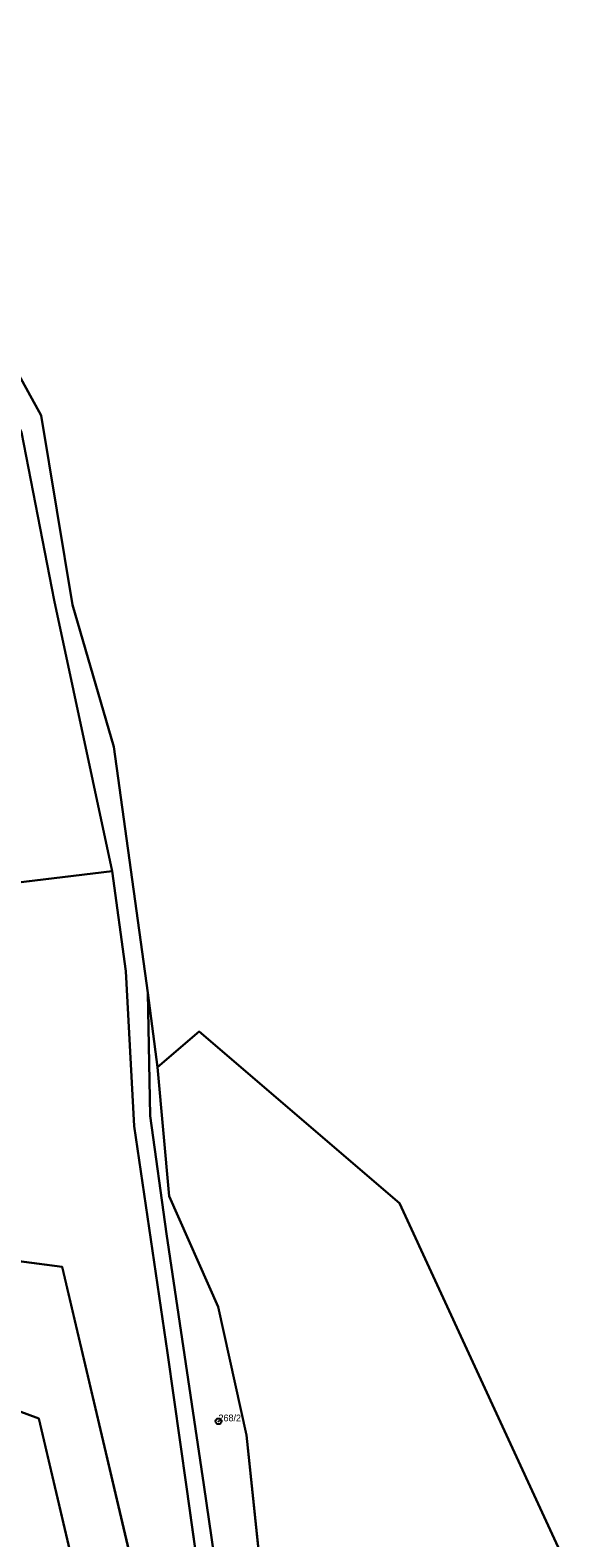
# Model space of a CAD drawing. Extents: x -652854 to -650068, y -1097661 to -1095417.
# Drawn here: x -651693.7 to -651554.5, y -1096486.9 to -1096107.3 of the extents above; entities that cross this region are included whole.
import ezdxf

# ---------------------------------------------------------------- set-up
doc = ezdxf.new("R2010")
doc.units = 0
for name, color, linetype in [('Definiční body parcel', 7, 'Continuous'), ('Hranice parcel', 7, 'Continuous'), ('Obvody jako plochy', 7, 'Continuous'), ('Parcelní čísla', 7, 'Continuous')]:
    doc.layers.add(name, color=color, linetype=linetype)

msp = doc.modelspace()

# ---------------------------------------------------------------- linework, layer by layer
at = {"layer": 'Definiční body parcel'}
for radius in [0.75, 0.0327]:
    msp.add_circle((-651646.29, -1096457.52), radius, dxfattribs=at)
at = {"layer": 'Hranice parcel'}
for p, q in [((-651690.95, -1096204.28), (-651728.47, -1096136.15)), ((-651683.01, -1096251.95), (-651690.95, -1096204.28)), ((-651695.89, -1096208.49), (-651687.67, -1096250.83)), ((-651687.67, -1096250.83), (-651673.04, -1096319.05)), ((-651672.67, -1096287.69), (-651683.01, -1096251.95)), ((-651664.09, -1096349.66), (-651672.67, -1096287.69)), ((-651673.04, -1096319.05), (-651710.67, -1096323.58)), ((-651673.04, -1096319.05), (-651669.61, -1096344.23)), ((-651669.61, -1096344.23), (-651667.53, -1096383.22)), ((-651664.09, -1096349.66), (-651663.46, -1096380.62)), ((-651661.63, -1096368.34), (-651664.09, -1096349.66)), ((-651651.15, -1096359.41), (-651661.63, -1096368.34)), ((-651600.66, -1096402.57), (-651651.15, -1096359.41)), ((-651658.71, -1096400.88), (-651661.63, -1096368.34)), ((-651663.46, -1096380.62), (-651659.4, -1096410.34)), ((-651667.53, -1096383.22), (-651659.12, -1096440.24)), ((-651646.4, -1096428.72), (-651658.71, -1096400.88)), ((-651555.25, -1096501.03), (-651600.66, -1096402.57)), ((-651685.67, -1096418.62), (-651785.42, -1096405.64)), ((-651659.4, -1096410.34), (-651650.01, -1096473.52)), ((-651663.59, -1096512.32), (-651685.67, -1096418.62)), ((-651639.25, -1096460.97), (-651646.4, -1096428.72)), ((-651691.55, -1096456.85), (-651747.93, -1096435.93)), ((-651654.35, -1096474.04), (-651659.12, -1096440.24)), ((-651666.79, -1096561.93), (-651691.55, -1096456.85)), ((-651634.91, -1096501.67), (-651639.25, -1096460.97)), ((-651650.01, -1096473.52), (-651636.3, -1096567.46)), ((-651654.35, -1096474.04), (-651642.8, -1096556.06))]:
    msp.add_line(p, q, dxfattribs=at)
at = {"layer": 'Obvody jako plochy'}
for points in [[(-651553.76, -1096093.05), (-651577.07, -1096086.78), (-651601.75, -1096075.97), (-651649.43, -1096071.53), (-651700.81, -1096041.54), (-651701.19, -1096046.05), (-651707.42, -1096048.55), (-651714.68, -1096051.04), (-651726.63, -1096058.67), (-651740.88, -1096077.97), (-651742.82, -1096091.89), (-651739.5, -1096109.16), (-651728.47, -1096136.15), (-651690.95, -1096204.28), (-651683.01, -1096251.95), (-651672.67, -1096287.69), (-651664.09, -1096349.66), (-651661.63, -1096368.34), (-651651.15, -1096359.41), (-651600.66, -1096402.57), (-651555.25, -1096501.03)], [(-651636.3, -1096567.46), (-651650.01, -1096473.52), (-651659.4, -1096410.34), (-651663.46, -1096380.62), (-651664.09, -1096349.66), (-651672.67, -1096287.69), (-651683.01, -1096251.95), (-651690.95, -1096204.28), (-651728.47, -1096136.15), (-651739.5, -1096109.16), (-651749.8, -1096112.77), (-651748.58, -1096115.33), (-651744.91, -1096121.76), (-651735.18, -1096138.78), (-651695.89, -1096208.49), (-651687.67, -1096250.83), (-651673.04, -1096319.05), (-651669.61, -1096344.23), (-651667.53, -1096383.22), (-651659.12, -1096440.24), (-651654.35, -1096474.04), (-651642.8, -1096556.06)], [(-651555.25, -1096501.03), (-651600.66, -1096402.57), (-651651.15, -1096359.41), (-651661.63, -1096368.34), (-651658.71, -1096400.88), (-651646.4, -1096428.72), (-651639.25, -1096460.97), (-651634.91, -1096501.67)]]:
    msp.add_lwpolyline(points, dxfattribs=at)
for points in [[(-651673.04, -1096319.05), (-651687.67, -1096250.83), (-651695.89, -1096208.49), (-651739.47, -1096210.32), (-651726.66, -1096252.14), (-651714.88, -1096279.19), (-651710.67, -1096323.58)], [(-651659.51, -1096555.13), (-651646.41, -1096555.8), (-651642.8, -1096556.06), (-651654.35, -1096474.04), (-651659.12, -1096440.24), (-651667.53, -1096383.22), (-651669.61, -1096344.23), (-651673.04, -1096319.05), (-651710.67, -1096323.58), (-651775.7, -1096331.44), (-651785.42, -1096405.64), (-651685.67, -1096418.62), (-651663.59, -1096512.32)], [(-651663.46, -1096380.62), (-651659.4, -1096410.34), (-651650.01, -1096473.52), (-651636.3, -1096567.46), (-651634.35, -1096543.17), (-651634.91, -1096501.67), (-651639.25, -1096460.97), (-651646.4, -1096428.72), (-651658.71, -1096400.88), (-651661.63, -1096368.34), (-651664.09, -1096349.66)], [(-651659.51, -1096555.13), (-651663.59, -1096512.32), (-651685.67, -1096418.62), (-651785.42, -1096405.64), (-651788.76, -1096431.88), (-651795.6, -1096461.91), (-651799.02, -1096481.47), (-651796.23, -1096492.24), (-651783.44, -1096503.05), (-651773.01, -1096517.88), (-651753.12, -1096532.75), (-651747.93, -1096435.93), (-651691.55, -1096456.85), (-651666.79, -1096561.93)], [(-651753.12, -1096532.75), (-651718.02, -1096559.55), (-651698.58, -1096568.61), (-651684.26, -1096565.06), (-651675.59, -1096560.88), (-651666.79, -1096561.93), (-651691.55, -1096456.85), (-651747.93, -1096435.93)]]:
    msp.add_lwpolyline(points, close=True, dxfattribs=at)

# ---------------------------------------------------------------- texts
at = {"layer": 'Parcelní čísla'}
msp.add_text('268/2', height=1.7, dxfattribs=at).set_placement((-651646.29, -1096457.52))

doc.saveas('drawing.dxf')
